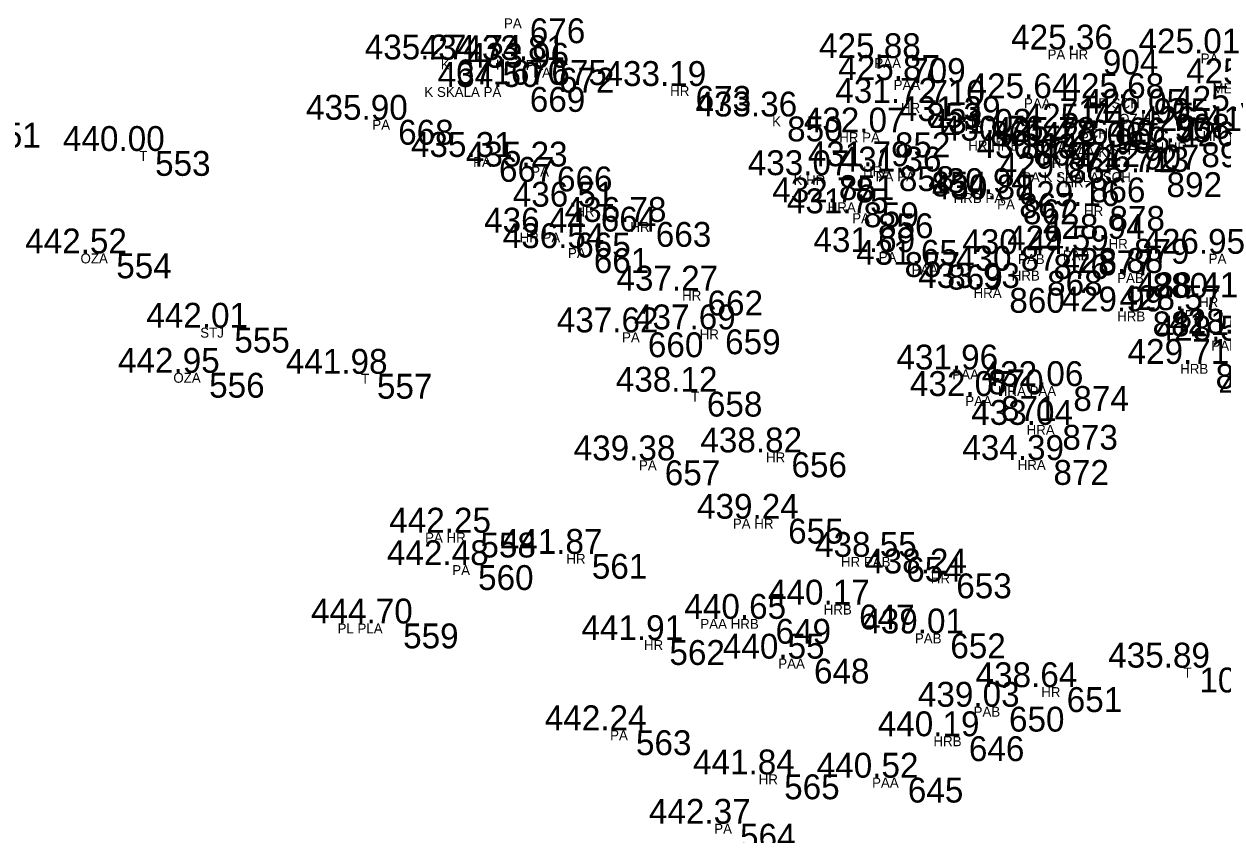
# Model space of a CAD drawing. Extents: x -639390 to -639075, y -1138747 to -1138358.
# Drawn here: x -639158.84 to -639122.71, y -1138697.01 to -1138672.58 of the extents above; entities that cross this region are included whole.
import ezdxf

# ---------------------------------------------------------------- set-up
doc = ezdxf.new("R2010")
doc.units = 0
for name, color, linetype in [('Vrstva 11', 7, 'Continuous'), ('Vrstva 12', 7, 'Continuous'), ('Vrstva 13', 7, 'Continuous'), ('Vrstva 57', 7, 'Continuous')]:
    doc.layers.add(name, color=color, linetype=linetype)

msp = doc.modelspace()

# ---------------------------------------------------------------- linework, layer by layer
at = {"layer": 'Vrstva 11'}
for p, q in [((-639146.09, -1138673.65), (-639146.09, -1138673.65)), ((-639144.43, -1138673.66), (-639144.43, -1138673.66)), ((-639143.21, -1138673.67), (-639143.21, -1138673.67)), ((-639132.39, -1138673.61), (-639132.39, -1138673.61)), ((-639126.58, -1138673.35), (-639126.58, -1138673.35)), ((-639122.85, -1138673.47), (-639122.85, -1138673.47)), ((-639142.98, -1138673.9), (-639142.98, -1138673.9)), ((-639131.81, -1138674.27), (-639131.81, -1138674.27)), ((-639143.86, -1138674.48), (-639143.86, -1138674.48)), ((-639138.86, -1138674.45), (-639138.86, -1138674.45)), ((-639131.9, -1138674.96), (-639131.9, -1138674.96)), ((-639127.88, -1138674.82), (-639127.88, -1138674.82)), ((-639125.05, -1138674.82), (-639125.05, -1138674.82)), ((-639147.83, -1138675.47), (-639147.83, -1138675.47)), ((-639136.1, -1138675.37), (-639136.1, -1138675.37)), ((-639124.42, -1138675.29), (-639124.42, -1138675.29)), ((-639132.85, -1138675.85), (-639132.85, -1138675.85)), ((-639129.98, -1138675.51), (-639129.98, -1138675.51)), ((-639126.22, -1138675.73), (-639126.22, -1138675.73)), ((-639122.8, -1138675.81), (-639122.8, -1138675.81)), ((-639129.05, -1138675.89), (-639129.05, -1138675.89)), ((-639128.67, -1138676.1), (-639128.67, -1138676.1)), ((-639127.13, -1138676.14), (-639127.13, -1138676.14)), ((-639123.61, -1138676.15), (-639123.61, -1138676.15)), ((-639155.16, -1138676.41), (-639155.16, -1138676.41)), ((-639125.65, -1138676.29), (-639125.65, -1138676.29)), ((-639125.34, -1138676.22), (-639125.34, -1138676.22)), ((-639144.79, -1138676.59), (-639144.79, -1138676.59)), ((-639143.04, -1138676.88), (-639143.04, -1138676.88)), ((-639132.73, -1138676.87), (-639132.73, -1138676.87)), ((-639127.64, -1138676.62), (-639127.64, -1138676.62)), ((-639134.54, -1138677.14), (-639134.54, -1138677.14)), ((-639131.75, -1138677.03), (-639131.75, -1138677.03)), ((-639126.97, -1138677.21), (-639126.97, -1138677.21)), ((-639124.66, -1138677.05), (-639124.66, -1138677.05)), ((-639133.8, -1138677.96), (-639133.8, -1138677.96)), ((-639129.1, -1138677.68), (-639129.1, -1138677.68)), ((-639128.99, -1138677.87), (-639128.99, -1138677.87)), ((-639141.72, -1138678.09), (-639141.72, -1138678.09)), ((-639133.36, -1138678.29), (-639133.36, -1138678.29)), ((-639126.38, -1138678.07), (-639126.38, -1138678.07)), ((-639140.06, -1138678.55), (-639140.06, -1138678.55)), ((-639142.49, -1138678.87), (-639142.49, -1138678.87)), ((-639125.64, -1138679.06), (-639125.64, -1138679.06)), ((-639141.93, -1138679.34), (-639141.93, -1138679.34)), ((-639132.56, -1138679.46), (-639132.56, -1138679.46)), ((-639126.72, -1138679.41), (-639126.72, -1138679.41)), ((-639156.33, -1138679.5), (-639156.33, -1138679.5)), ((-639128.07, -1138679.52), (-639128.07, -1138679.52)), ((-639131.27, -1138679.84), (-639131.27, -1138679.84)), ((-639128.26, -1138680.02), (-639128.26, -1138680.02)), ((-639125.08, -1138680.09), (-639125.08, -1138680.09)), ((-639129.4, -1138680.54), (-639129.4, -1138680.54)), ((-639138.5, -1138680.62), (-639138.5, -1138680.62)), ((-639122.91, -1138680.82), (-639122.91, -1138680.82)), ((-639125.08, -1138681.25), (-639125.08, -1138681.25)), ((-639123.33, -1138681.21), (-639123.33, -1138681.21)), ((-639152.77, -1138681.74), (-639152.77, -1138681.74)), ((-639140.3, -1138681.88), (-639140.3, -1138681.88)), ((-639137.97, -1138681.79), (-639137.97, -1138681.79)), ((-639130.04, -1138683), (-639130.04, -1138683)), ((-639123.18, -1138682.83), (-639123.18, -1138682.83)), ((-639153.53, -1138683.1), (-639153.53, -1138683.1)), ((-639148.47, -1138683.13), (-639148.47, -1138683.13)), ((-639138.52, -1138683.67), (-639138.52, -1138683.67)), ((-639129.65, -1138683.8), (-639129.65, -1138683.8)), ((-639127.47, -1138683.5), (-639127.47, -1138683.5)), ((-639127.8, -1138684.67), (-639127.8, -1138684.67)), ((-639135.97, -1138685.5), (-639135.97, -1138685.5)), ((-639139.79, -1138685.74), (-639139.79, -1138685.74)), ((-639128.07, -1138685.73), (-639128.07, -1138685.73)), ((-639136.07, -1138687.5), (-639136.07, -1138687.5)), ((-639145.35, -1138687.92), (-639145.35, -1138687.92)), ((-639141.99, -1138688.56), (-639141.99, -1138688.56)), ((-639132.51, -1138688.65), (-639132.51, -1138688.65)), ((-639145.42, -1138688.9), (-639145.42, -1138688.9)), ((-639131, -1138689.15), (-639131, -1138689.15)), ((-639133.93, -1138690.09), (-639133.93, -1138690.09)), ((-639147.68, -1138690.66), (-639147.68, -1138690.66)), ((-639136.45, -1138690.52), (-639136.45, -1138690.52)), ((-639131.18, -1138690.96), (-639131.18, -1138690.96)), ((-639139.65, -1138691.16), (-639139.65, -1138691.16)), ((-639135.29, -1138691.72), (-639135.29, -1138691.72)), ((-639123.67, -1138691.99), (-639123.67, -1138691.99)), ((-639127.67, -1138692.58), (-639127.67, -1138692.58)), ((-639129.41, -1138693.17), (-639129.41, -1138693.17)), ((-639140.66, -1138693.88), (-639140.66, -1138693.88)), ((-639130.62, -1138694.06), (-639130.62, -1138694.06)), ((-639136.19, -1138695.21), (-639136.19, -1138695.21)), ((-639132.46, -1138695.31), (-639132.46, -1138695.31)), ((-639137.52, -1138696.7), (-639137.52, -1138696.7))]:
    msp.add_line(p, q, dxfattribs=at)

# ---------------------------------------------------------------- texts
at = {"layer": 'Vrstva 12'}
for s, p in [('425.36 ', (-639129.066, -1138673.35)), ('435.27 ', (-639148.559, -1138673.65)), ('434.74 ', (-639146.899, -1138673.66)), ('433.81 ', (-639145.585, -1138673.67)), ('425.88 ', (-639134.859, -1138673.61)), ('425.01 ', (-639125.225, -1138673.47)), ('433.96 ', (-639145.466, -1138673.9)), ('425.87 ', (-639134.279, -1138674.27)), ('425.18 ', (-639123.789, -1138674.37)), ('434.50 ', (-639146.359, -1138674.48)), ('433.19 ', (-639141.329, -1138674.45)), ('431.72 ', (-639134.369, -1138674.96)), ('425.64 ', (-639130.349, -1138674.82)), ('425.68 ', (-639127.519, -1138674.82)), ('435.90 ', (-639150.329, -1138675.47)), ('433.36 ', (-639138.586, -1138675.37)), ('431.39 ', (-639132.449, -1138675.51)), ('426.05 ', (-639126.89, -1138675.29)), ('425.62 ', (-639124.149, -1138675.2)), ('432.07 ', (-639135.319, -1138675.85)), ('431.03 ', (-639131.519, -1138675.89)), ('425.74 ', (-639128.689, -1138675.73)), ('426.41 ', (-639125.175, -1138675.81)), ('430.76 ', (-639131.156, -1138676.1)), ('425.78 ', (-639129.599, -1138676.14)), ('426.09 ', (-639127.809, -1138676.22)), ('426.55 ', (-639126.08, -1138676.15)), ('440.00 ', (-639157.659, -1138676.41)), ('435.31 ', (-639147.165, -1138676.59)), ('426.06 ', (-639128.136, -1138676.29)), ('426.49 ', (-639123.999, -1138676.27)), ('435.23 ', (-639145.509, -1138676.88)), ('431.79 ', (-639135.199, -1138676.87)), ('430.14 ', (-639130.109, -1138676.62)), ('433.07 ', (-639137.009, -1138677.14)), ('431.36 ', (-639134.236, -1138677.03)), ('429.67 ', (-639129.439, -1138677.21)), ('426.72 ', (-639127.129, -1138677.05)), ('430.94 ', (-639131.569, -1138677.68)), ('432.78 ', (-639136.269, -1138677.96)), ('430.88 ', (-639131.459, -1138677.87)), ('436.51 ', (-639144.095, -1138678.09)), ('431.75 ', (-639135.83, -1138678.29)), ('429.16 ', (-639128.866, -1138678.07)), ('436.78 ', (-639142.529, -1138678.55)), ('436.44 ', (-639144.959, -1138678.87)), ('428.94 ', (-639128.109, -1138679.06)), ('442.52 ', (-639158.799, -1138679.5)), ('436.54 ', (-639144.399, -1138679.34)), ('431.69 ', (-639135.029, -1138679.46)), ('429.59 ', (-639129.189, -1138679.41)), ('431.65 ', (-639133.74, -1138679.84)), ('430.44 ', (-639130.539, -1138679.52)), ('426.95 ', (-639125.08, -1138679.51)), ('430.87 ', (-639130.729, -1138680.02)), ('428.88 ', (-639127.549, -1138680.09)), ('433.93 ', (-639131.869, -1138680.54)), ('437.27 ', (-639140.969, -1138680.62)), ('428.41 ', (-639125.285, -1138680.82)), ('429.99 ', (-639127.549, -1138681.25)), ('428.57 ', (-639125.799, -1138681.21)), ('442.01 ', (-639155.145, -1138681.74)), ('437.62 ', (-639142.769, -1138681.88)), ('437.69 ', (-639140.439, -1138681.79)), ('428.40 ', (-639124.299, -1138681.92)), ('428.58 ', (-639124.709, -1138682.13)), ('442.95 ', (-639156, -1138683.1)), ('431.96 ', (-639132.526, -1138683)), ('429.71 ', (-639125.555, -1138682.83)), ('441.98 ', (-639150.939, -1138683.13)), ('438.12 ', (-639140.989, -1138683.67)), ('432.07 ', (-639132.119, -1138683.8)), ('432.06 ', (-639129.956, -1138683.5)), ('428.68 ', (-639122.789, -1138683.87)), ('433.04 ', (-639130.269, -1138684.67)), ('438.82 ', (-639138.439, -1138685.5)), ('439.38 ', (-639142.259, -1138685.74)), ('434.39 ', (-639130.539, -1138685.73)), ('439.24 ', (-639138.539, -1138687.5)), ('442.25 ', (-639147.82, -1138687.92)), ('442.48 ', (-639147.889, -1138688.9)), ('441.87 ', (-639144.459, -1138688.56)), ('438.55 ', (-639134.98, -1138688.65)), ('438.24 ', (-639133.469, -1138689.15)), ('440.17 ', (-639136.399, -1138690.09)), ('444.70 ', (-639150.179, -1138690.66)), ('440.65 ', (-639138.92, -1138690.52)), ('439.01 ', (-639133.555, -1138690.96)), ('441.91 ', (-639142.025, -1138691.16)), ('440.55 ', (-639137.76, -1138691.72)), ('435.89 ', (-639126.139, -1138691.99)), ('438.64 ', (-639130.139, -1138692.58)), ('439.03 ', (-639131.879, -1138693.17)), ('442.24 ', (-639143.129, -1138693.88)), ('440.19 ', (-639133.089, -1138694.06)), ('441.84 ', (-639138.659, -1138695.21)), ('440.52 ', (-639134.929, -1138695.31)), ('442.37 ', (-639139.989, -1138696.7))]:
    msp.add_text(s, height=0.75, dxfattribs=at).set_placement(p)
at = {"layer": 'Vrstva 13'}
for s, p in [(' 676', (-639143.86, -1138673.16)), (' 671', (-639146.09, -1138674.4)), (' 670', (-639144.43, -1138674.41)), (' 675', (-639143.21, -1138674.42)), (' 709', (-639132.39, -1138674.36)), (' 904', (-639126.58, -1138674.1)), (' 672', (-639142.98, -1138674.65)), (' 710', (-639131.81, -1138675.02)), (' 669', (-639143.86, -1138675.23)), (' 673', (-639138.86, -1138675.2)), (' 853', (-639131.9, -1138675.71)), (' 711', (-639127.88, -1138675.57)), (' 905', (-639125.05, -1138675.57)), (' 668', (-639147.83, -1138676.22)), (' 850', (-639136.1, -1138676.12)), (' 908', (-639124.42, -1138676.04)), (' 551', (-639160.28, -1138676.31)), (' 852', (-639132.85, -1138676.6)), (' 861', (-639129.98, -1138676.26)), (' 906', (-639126.22, -1138676.48)), (' 863', (-639129.05, -1138676.64)), (' 864', (-639128.67, -1138676.85)), (' 712', (-639127.13, -1138676.89)), (' 907', (-639125.34, -1138676.97)), (' 893', (-639123.61, -1138676.9)), (' 553', (-639155.16, -1138677.16)), (' 713', (-639125.65, -1138677.04)), (' 667', (-639144.79, -1138677.34)), (' 666', (-639143.04, -1138677.63)), (' 858', (-639132.73, -1138677.62)), (' 865', (-639127.64, -1138677.37)), (' 851', (-639134.54, -1138677.89)), (' 854', (-639131.75, -1138677.78)), (' 866', (-639126.97, -1138677.96)), (' 892', (-639124.66, -1138677.8)), (' 859', (-639133.8, -1138678.71)), (' 867', (-639129.1, -1138678.43)), (' 862', (-639128.99, -1138678.62)), (' 664', (-639141.72, -1138678.84)), (' 856', (-639133.36, -1138679.04)), (' 878', (-639126.38, -1138678.82)), (' 663', (-639140.06, -1138679.3)), (' 665', (-639142.49, -1138679.62)), (' 879', (-639125.64, -1138679.81)), (' 661', (-639141.93, -1138680.09)), (' 857', (-639132.56, -1138680.21)), (' 877', (-639126.72, -1138680.16)), (' 554', (-639156.33, -1138680.25)), (' 869', (-639131.27, -1138680.59)), (' 876', (-639128.07, -1138680.27)), (' 868', (-639128.26, -1138680.77)), (' 880', (-639125.08, -1138680.84)), (' 860', (-639129.4, -1138681.29)), (' 662', (-639138.5, -1138681.37)), (' 881', (-639125.08, -1138682)), (' 1069', (-639123.33, -1138681.96)), (' 555', (-639152.77, -1138682.49)), (' 660', (-639140.3, -1138682.63)), (' 659', (-639137.97, -1138682.54)), (' 870', (-639130.04, -1138683.75)), (' 882', (-639123.18, -1138683.58)), (' 556', (-639153.53, -1138683.85)), (' 557', (-639148.47, -1138683.88)), (' 658', (-639138.52, -1138684.42)), (' 871', (-639129.65, -1138684.55)), (' 874', (-639127.47, -1138684.25)), (' 873', (-639127.8, -1138685.42)), (' 656', (-639135.97, -1138686.25)), (' 657', (-639139.79, -1138686.49)), (' 872', (-639128.07, -1138686.48)), (' 655', (-639136.07, -1138688.25)), (' 558', (-639145.35, -1138688.67)), (' 561', (-639141.99, -1138689.31)), (' 654', (-639132.51, -1138689.4)), (' 560', (-639145.42, -1138689.65)), (' 653', (-639131, -1138689.9)), (' 647', (-639133.93, -1138690.84)), (' 559', (-639147.68, -1138691.41)), (' 649', (-639136.45, -1138691.27)), (' 652', (-639131.18, -1138691.71)), (' 562', (-639139.65, -1138691.91)), (' 648', (-639135.29, -1138692.47)), (' 1071', (-639123.67, -1138692.74)), (' 651', (-639127.67, -1138693.33)), (' 650', (-639129.41, -1138693.92)), (' 563', (-639140.66, -1138694.63)), (' 646', (-639130.62, -1138694.81)), (' 565', (-639136.19, -1138695.96)), (' 645', (-639132.46, -1138696.06)), (' 564', (-639137.52, -1138697.45))]:
    msp.add_text(s, height=0.75, dxfattribs=at).set_placement(p)
at = {"layer": 'Vrstva 57'}
for s, p in [('PA', (-639144.36, -1138672.71)), ('K', (-639146.265, -1138673.95)), ('K', (-639144.605, -1138673.96)), ('PA', (-639143.71, -1138673.97)), ('PAA', (-639133.19, -1138673.91)), ('PA HR', (-639127.969, -1138673.65)), ('PA', (-639123.35, -1138673.77)), ('PA', (-639143.48, -1138674.2)), ('PAA', (-639132.61, -1138674.57)), ('MEZNIK', (-639122.995, -1138674.67)), ('K SKALA PA', (-639146.76, -1138674.78)), ('HR', (-639139.349, -1138674.75)), ('HR', (-639132.389, -1138675.26)), ('PAA', (-639128.68, -1138675.12)), ('HR SCH', (-639126.725, -1138675.12)), ('PA', (-639148.33, -1138675.77)), ('K', (-639136.275, -1138675.67)), ('OZ HR', (-639125.809, -1138675.59)), ('HR PA', (-639134.25, -1138676.15)), ('HR', (-639130.469, -1138675.81)), ('SCH', (-639126.995, -1138676.03)), ('HR', (-639123.289, -1138676.11)), ('HR HRB', (-639130.359, -1138676.4)), ('HR', (-639129.539, -1138676.19)), ('PAA', (-639127.93, -1138676.44)), ('SCH', (-639126.115, -1138676.52)), ('SCH HR', (-639125.299, -1138676.45)), ('T', (-639155.36, -1138676.71)), ('PAA KA', (-639127.35, -1138676.59)), ('PA', (-639145.29, -1138676.89)), ('PA', (-639143.54, -1138677.18)), ('HRA', (-639133.53, -1138677.17)), ('HR', (-639128.129, -1138676.92)), ('K HR', (-639135.629, -1138677.44)), ('PA PA', (-639133.15, -1138677.33)), ('PA K SKALA SCH', (-639128.735, -1138677.35)), ('HR', (-639127.459, -1138677.51)), ('HRA', (-639134.6, -1138678.26)), ('HRB PA', (-639130.8, -1138677.98)), ('PA', (-639129.49, -1138678.17)), ('HR', (-639142.209, -1138678.39)), ('PA', (-639133.86, -1138678.59)), ('HR', (-639126.869, -1138678.37)), ('HR', (-639140.549, -1138678.85)), ('HR PA', (-639143.89, -1138679.17)), ('HR', (-639126.129, -1138679.36)), ('PA', (-639142.43, -1138679.64)), ('PA', (-639133.06, -1138679.76)), ('PAB', (-639127.509, -1138679.71)), ('OZA', (-639157.13, -1138679.8)), ('PAB', (-639128.859, -1138679.82)), ('PA', (-639123.11, -1138679.81)), ('PAA', (-639132.07, -1138680.14)), ('HRB', (-639129.049, -1138680.32)), ('PAB', (-639125.869, -1138680.39)), ('HRA', (-639130.2, -1138680.84)), ('HR', (-639138.989, -1138680.92)), ('HR', (-639123.399, -1138681.12)), ('HRB', (-639125.869, -1138681.55)), ('PA', (-639123.83, -1138681.51)), ('STJ', (-639153.52, -1138682.04)), ('PA', (-639140.8, -1138682.18)), ('HR', (-639138.459, -1138682.09)), ('PAB', (-639123.029, -1138682.43)), ('PAA', (-639130.84, -1138683.3)), ('HRB', (-639123.969, -1138683.13)), ('OZA', (-639154.33, -1138683.4)), ('T', (-639148.67, -1138683.43)), ('T', (-639138.72, -1138683.97)), ('PAA', (-639130.45, -1138684.1)), ('HRA PAA', (-639129.47, -1138683.8)), ('HRA', (-639128.6, -1138684.97)), ('HR', (-639136.459, -1138685.8)), ('PA', (-639140.29, -1138686.04)), ('HRA', (-639128.87, -1138686.03)), ('PA HR', (-639137.459, -1138687.8)), ('PA HR', (-639146.739, -1138688.22)), ('HR', (-639142.479, -1138688.86)), ('HR PAB', (-639134.199, -1138688.95)), ('PA', (-639145.92, -1138689.2)), ('HR', (-639131.489, -1138689.45)), ('HRB', (-639134.719, -1138690.39)), ('PL PLA', (-639149.38, -1138690.96)), ('PAA HRB', (-639138.439, -1138690.82)), ('PAB', (-639131.969, -1138691.26)), ('HR', (-639140.139, -1138691.46)), ('PAA', (-639136.09, -1138692.02)), ('T', (-639123.87, -1138692.29)), ('HR', (-639128.159, -1138692.88)), ('PAB', (-639130.199, -1138693.47)), ('PA', (-639141.16, -1138694.18)), ('HRB', (-639131.409, -1138694.36)), ('HR', (-639136.679, -1138695.51)), ('PAA', (-639133.26, -1138695.61)), ('PA', (-639138.02, -1138697))]:
    msp.add_text(s, height=0.3, dxfattribs=at).set_placement(p)

doc.saveas('drawing.dxf')
